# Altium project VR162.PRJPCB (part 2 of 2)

## Sheet 14 TP.SchDoc
size 246 x 182 mm
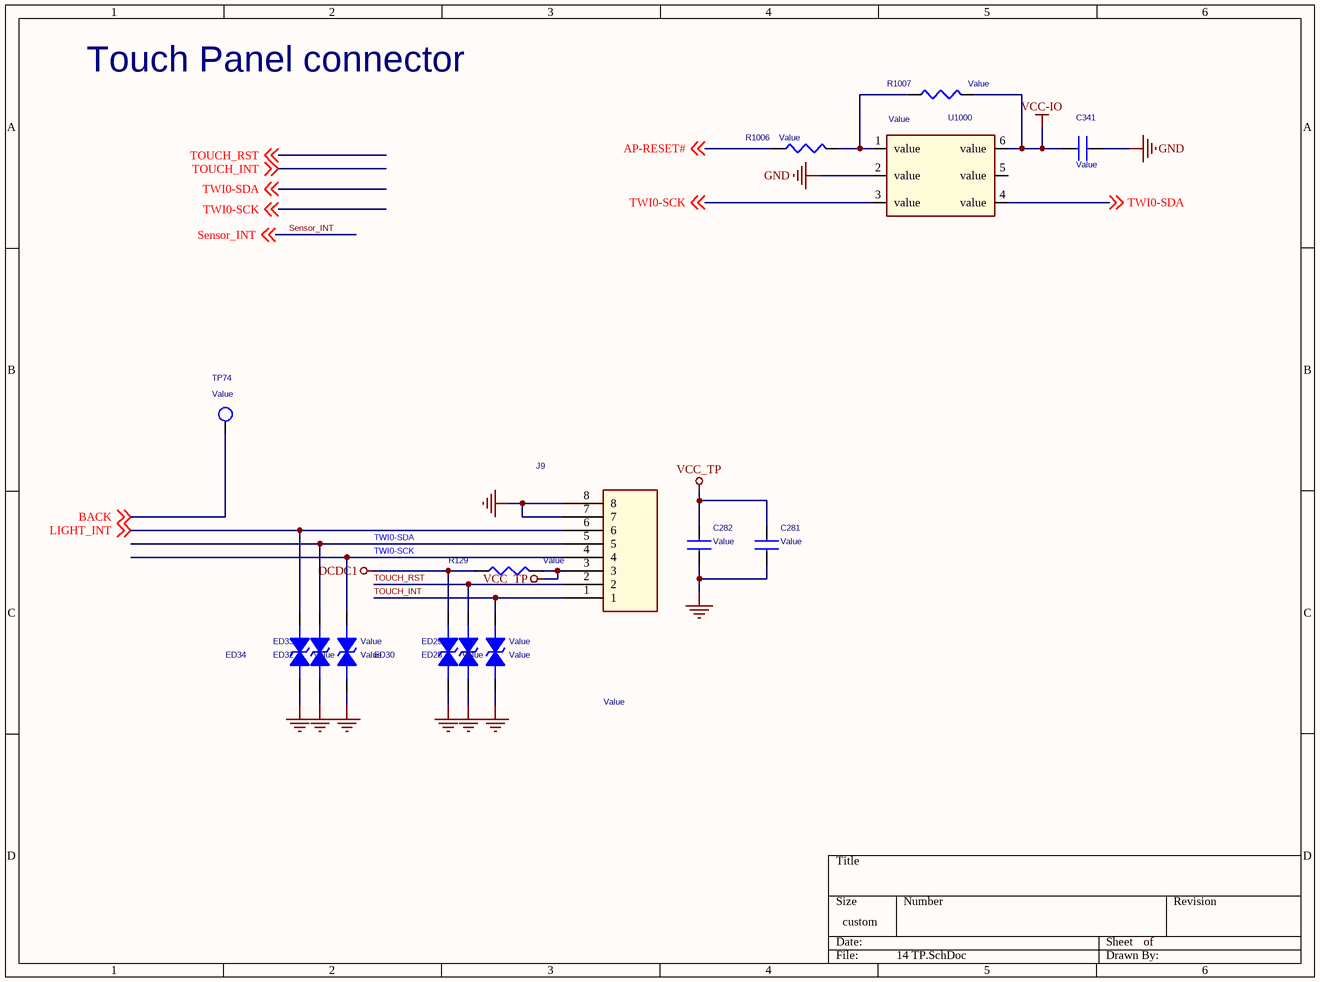
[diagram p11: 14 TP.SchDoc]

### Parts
C281  Value  [C0603]
C282  Value  [C0603]
C341  Value  [C0603]
ED28  Value  [R0402]
ED29  Value  [R0402]
ED30  Value  [R0402]
ED32  Value  [R0402]
ED33  Value  [R0402]
ED34  Value  [R0402]
J9  Value  [FPC8-PT0.5-H1_9A]
R129  Value  [R0402]
R1006  Value  [R0402]
R1007  Value  [R0402]
TP74  Value  [TP_SMD]
U1000  Value  [SOT23-6]

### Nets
DCDC1: C341.1 ED30.1 R129.1 R1007.2 U1000.6(value)  [also labelled VCC-IO]
GND: C281.2 C282.2 C341.2 ED28.2 ED29.2 ED30.2 ED32.2 ED33.2 ED34.2 J9.7 J9.8 U1000.2(value)
VCC_TP: C281.1 C282.1 J9.3 R129.2
AP-RESET#: R1006.1 ; off-sheet AP-RESET#
BACK: TP74.1(TP) ; off-sheet BACK
LIGHT_INT: ED34.1 J9.6 ; off-sheet LIGHT_INT
TOUCH_INT: ED28.1 J9.1 ; off-sheet TOUCH_INT
TOUCH_RST: ED29.1 J9.2 ; off-sheet TOUCH_RST
TWI0-SCK: ED32.1 J9.4 U1000.3(value) ; off-sheet TWI0-SCK  [project net SENSOR0-TWI-SCK]
TWI0-SDA: ED33.1 J9.5 U1000.4(value) ; off-sheet TWI0-SDA  [project net SENSOR0-TWI-SDA]
NetR1006_2: R1006.2 R1007.1 U1000.1(value)

Not connected (* = marked no-connect by the designer): U1000 5(value)

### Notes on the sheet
- Touch Panel connector

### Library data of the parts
C281 = CAP NP: CAP,MLCC,100nF,+/-10%,X7R,6.3V,SMD0402
C282 C341 = CAP NP
ED28-ED30 ED32-ED34 = DIODE BI-DIR TRIG: ESD
J9 = touch_screen_1
R129 = RESISTOR_Dup1: RES,thick film,33Ohm,+/-5%,1/16W,SMD0402
R1006 R1007 = R_Dup2
TP74 = T_POINT_R
U1000 = LM1086_2

## Sheet 09 CAMERA.SchDoc
size 386 x 246 mm
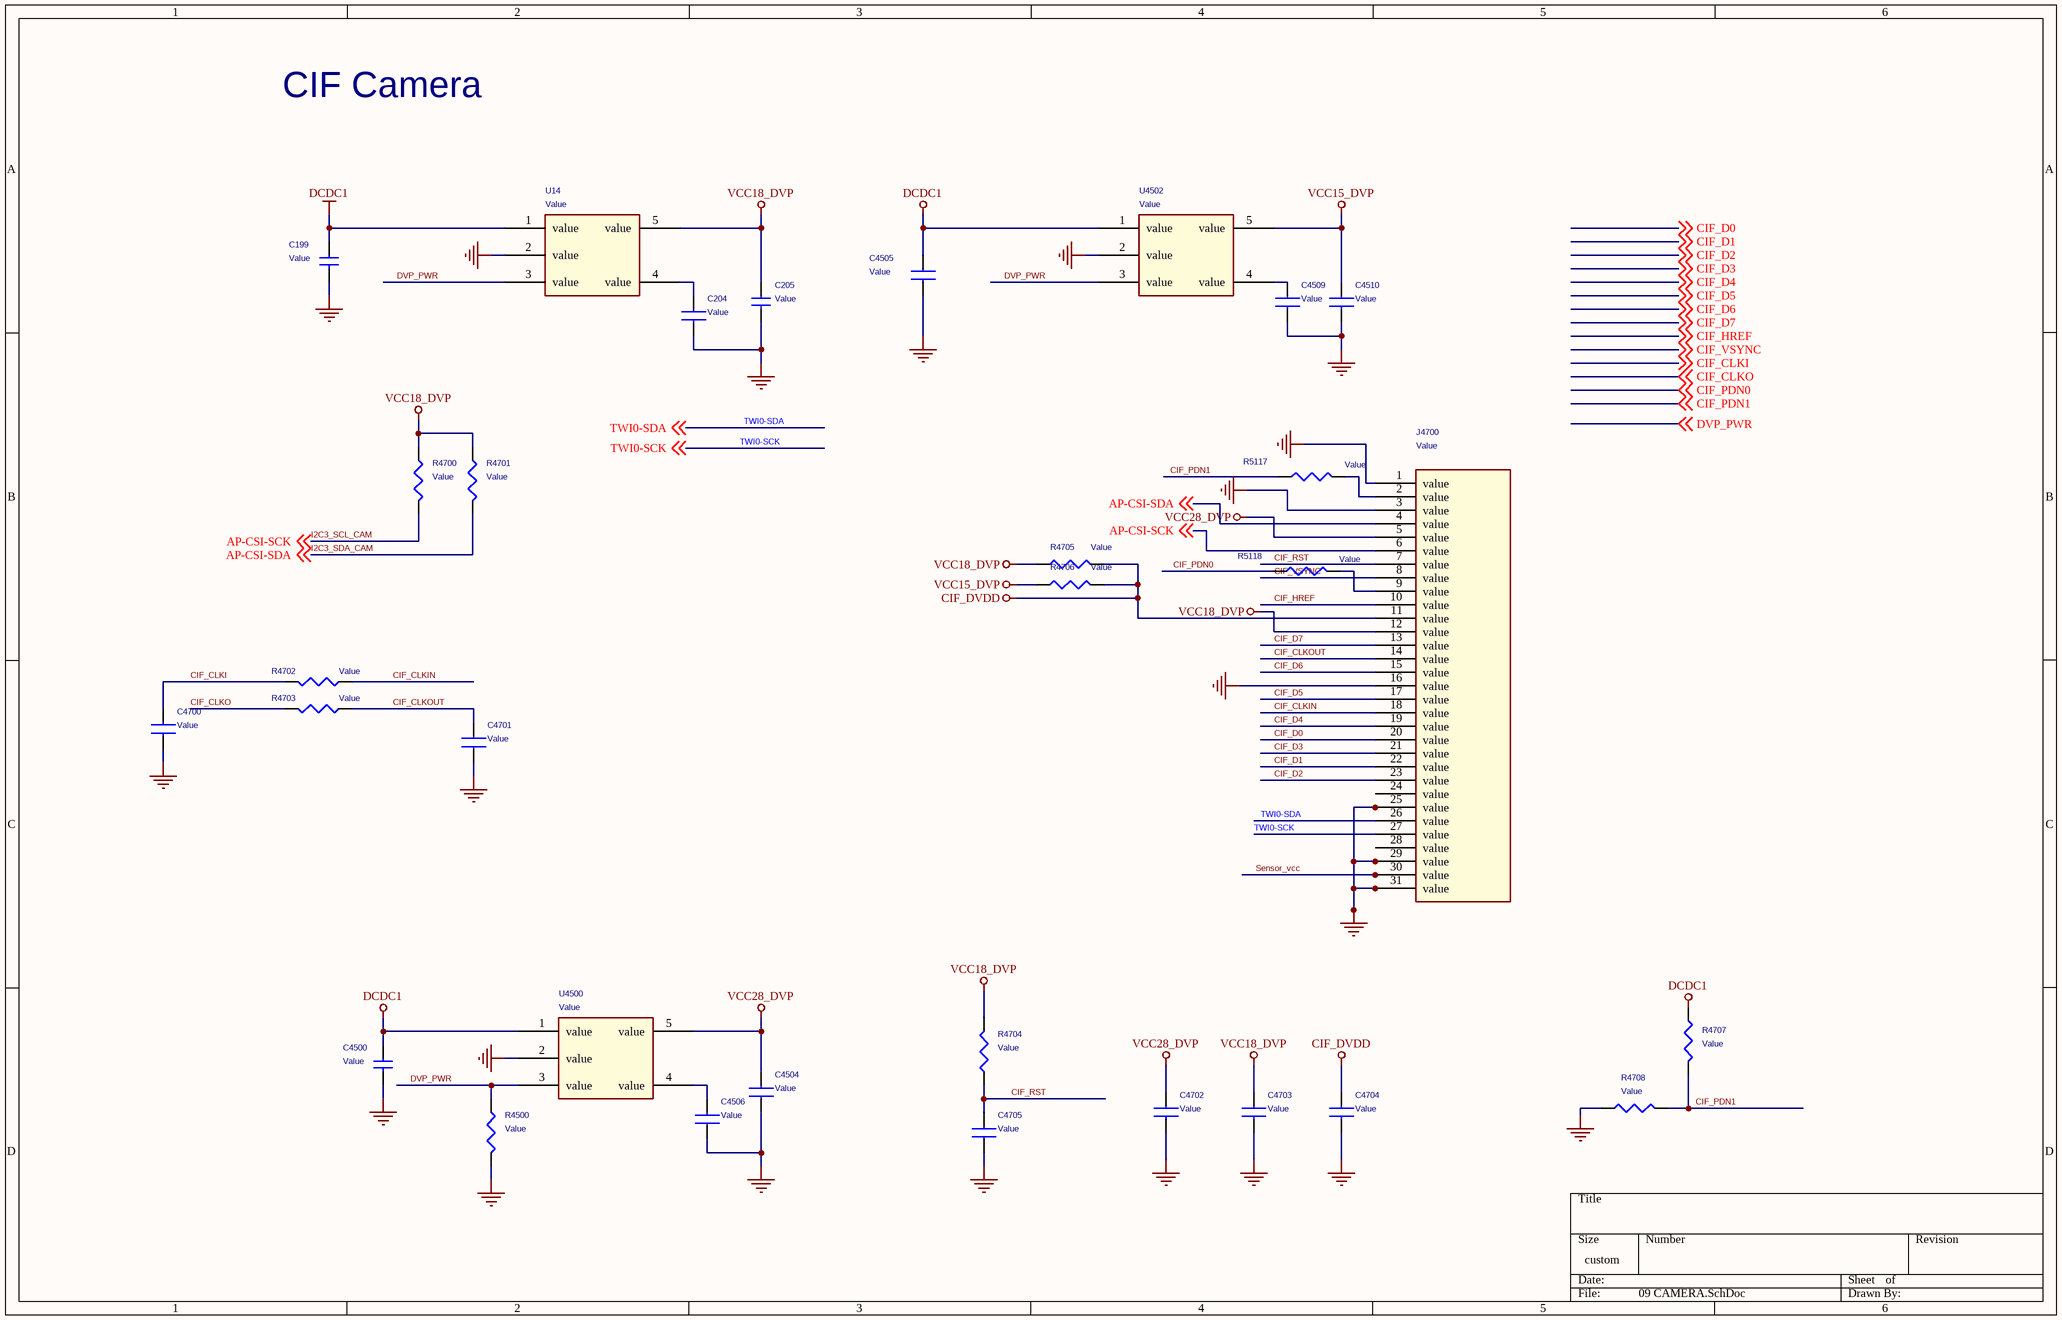
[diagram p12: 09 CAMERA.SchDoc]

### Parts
C199  Value  [C0603]
C204  Value  [C0603]
C205  Value  [C0603]
C4500  Value  [C0603]
C4504  Value  [C0603]
C4505  Value  [C0603]
C4506  Value  [C0603]
C4509  Value  [C0603]
C4510  Value  [C0603]
C4700  Value  [C0603]
C4701  Value  [C0603]
C4702  Value  [C0603]
C4703  Value  [C0603]
C4704  Value  [C0603]
C4705  Value  [C0603]
J4700  Value  [AYF333135]
R4500  Value  [R0402]
R4700  Value  [R0402]
R4701  Value  [R0402]
R4702  Value  [R0402]
R4703  Value  [R0402]
R4704  Value  [R0402]
R4705  Value  [R0402]
R4706  Value  [R0402]
R4707  Value  [R0402]
R4708  Value  [R0402]
R5117  Value  [R0402]
R5118  Value  [R0402]
U14  Value  [SOT23_5H14A]
U4500  Value  [SOT23_5H14A]
U4502  Value  [SOT23_5H14A]

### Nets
CIF_DVDD: C4704.2 J4700.11(value) R4705.2 R4706.2
DCDC1: C199.1 C4500.1 C4505.1 R4707.1 U14.1(value) U4500.1(value) U4502.1(value)
GND: C199.2 C204.2 C205.2 C4500.2 C4504.2 C4505.2 C4506.2 C4509.2 C4510.1 C4700.1 C4701.1 C4702.2 C4703.2 C4704.1 C4705.1 J4700.1(value) J4700.3(value) J4700.16(value) J4700.25(value) J4700.29(value) J4700.31(value) R4500.2 R4708.1 U14.2(value) U4500.2(value) U4502.2(value)
VCC15_DVP: C4510.2 R4706.1 U4502.5(value)
VCC18_DVP: C205.1 C4703.1 J4700.12(value) R4700.1 R4701.1 R4704.2 R4705.1 U14.5(value)
VCC28_DVP: C4504.1 C4702.1 J4700.5(value) U4500.5(value)
CIF_CLKI: C4700.2 R4702.2 ; off-sheet CIF_CLKI
CIF_CLKIN: J4700.18(value) R4702.1
CIF_CLKO: R4703.2 ; off-sheet CIF_CLKO
CIF_CLKOUT: C4701.2 J4700.14(value) R4703.1
CIF_D0: J4700.20(value) ; off-sheet CIF_D0
CIF_D1: J4700.22(value) ; off-sheet CIF_D1
CIF_D2: J4700.23(value) ; off-sheet CIF_D2
CIF_D3: J4700.21(value) ; off-sheet CIF_D3
CIF_D4: J4700.19(value) ; off-sheet CIF_D4
CIF_D5: J4700.17(value) ; off-sheet CIF_D5
CIF_D6: J4700.15(value) ; off-sheet CIF_D6
CIF_D7: J4700.13(value) ; off-sheet CIF_D7
CIF_HREF: J4700.10(value) ; off-sheet CIF_HREF
CIF_PDN0: R5118.1 ; off-sheet CIF_PDN0
CIF_PDN1: R4707.2 R4708.2 R5117.1 ; off-sheet CIF_PDN1
CIF_RST: C4705.2 J4700.7(value) R4704.1
CIF_VSYNC: J4700.8(value) ; off-sheet CIF_VSYNC
DVP_PWR: R4500.1 U14.3(value) U4500.3(value) U4502.3(value) ; off-sheet DVP_PWR
I2C3_SCL_CAM: J4700.6(value) R4700.2 ; off-sheet AP-CSI-SCK  [also labelled AP-CSI-SCK]
I2C3_SDA_CAM: J4700.4(value) R4701.2 ; off-sheet AP-CSI-SDA  [also labelled AP-CSI-SDA]
Sensor_vcc: J4700.30(value)
TWI0-SCK: J4700.27(value) ; off-sheet TWI0-SCK  [project net SENSOR0-TWI-SCK]
TWI0-SDA: J4700.26(value) ; off-sheet TWI0-SDA  [project net SENSOR0-TWI-SDA]
NetC204_1: C204.1 U14.4(value)
NetC4506_1: C4506.1 U4500.4(value)
NetC4509_1: C4509.1 U4502.4(value)
NetJ4700_2: J4700.2(value) R5117.2
NetJ4700_9: J4700.9(value) R5118.2

Not connected (* = marked no-connect by the designer): J4700 24(value) 28(value)

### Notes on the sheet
- CIF Camera

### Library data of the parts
C199 C205 C4500 = SMALL CAP: 贴片电容
C204 C4505 C4506 C4509 C4510 = CAP NP
C4504 C4705 = CAP NP: CAP,MLCC,100nF,+/-10%,X7R,6.3V,SMD0402
C4700 C4701 = CAP NP: CAP,MLCC,8pF,+/-10%,NPO,6.3V,SMD0402
C4702-C4704 = CAP NP: CAP,MLCC,1uF,+/-10%,X5R,6.3V,SMD0402
J4700 = LCM0200CE1A0_2: Camera Conncetor, 24pin,SMT
R4500 = RES 1B
R4700 R4701 R4705-R4708 R5117 R5118 = RESISTOR_0_Dup1
R4702 R4703 = RESISTOR_0: RES,thick film,22Ohm,+/-5%,1/16W,SMD0402
R4704 = RESISTOR: NC
U14 U4500 U4502 = LDO-PT5108/RT9013_0

## Sheet 15 SENSOR.SchDoc
size 386 x 246 mm
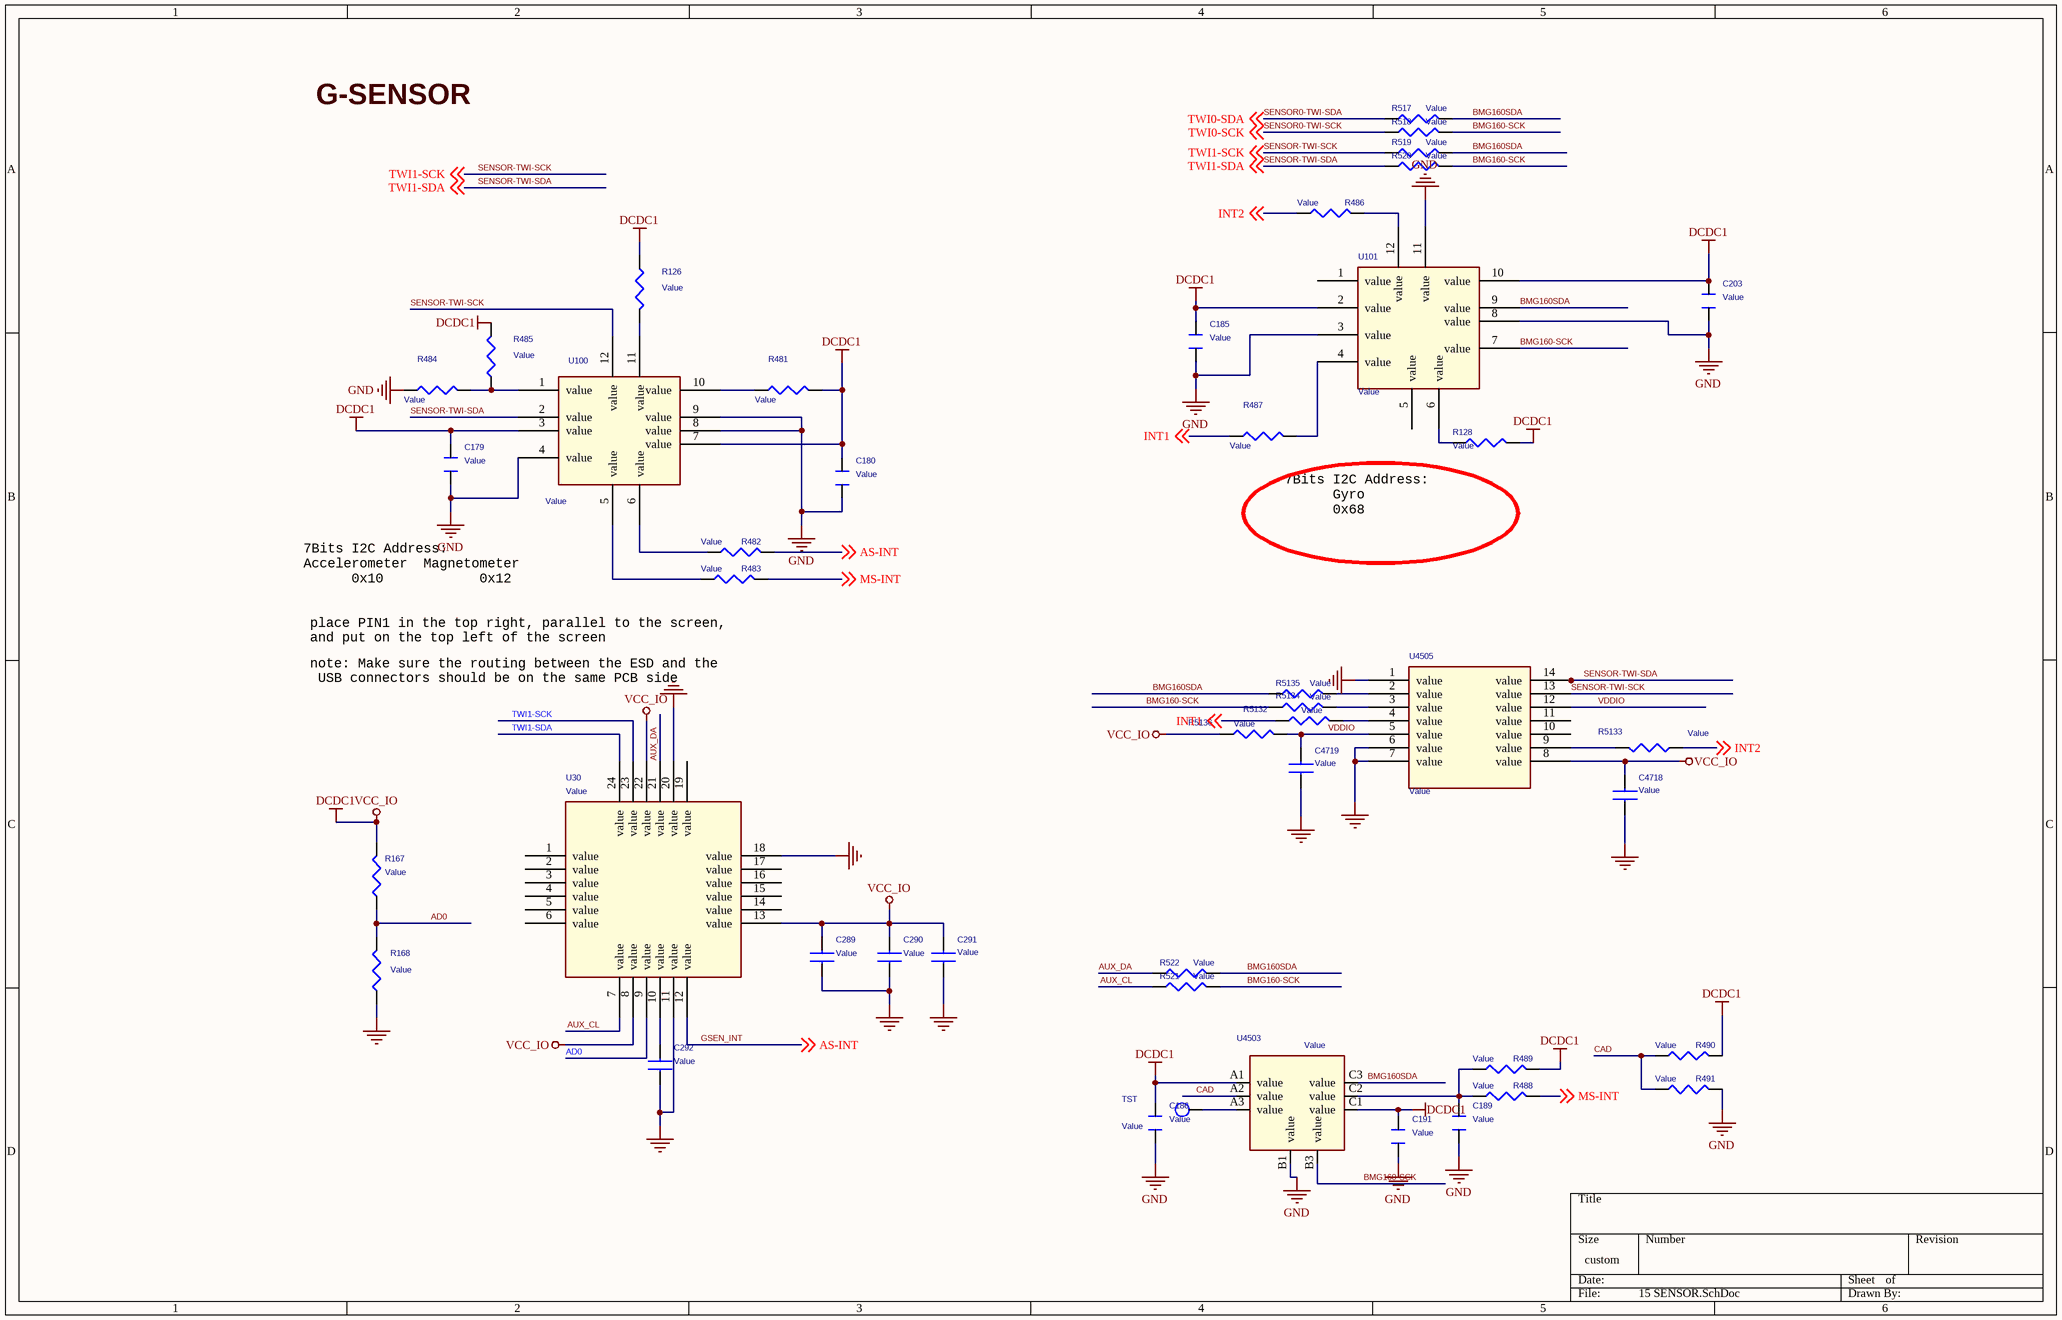
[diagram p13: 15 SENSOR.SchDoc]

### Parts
C179  Value  [C0402]
C180  Value  [C0402]
C185  Value  [C0402]
C186  Value  [C0402]
C189  Value  [C0402]
C191  Value  [C0402]
C203  Value  [C0402]
C289  Value  [C0603]
C290  Value  [C0603]
C291  Value  [C0603]
C292  Value  [C0603]
C4718  Value  [C0603]
C4719  Value  [C0603]
R126  Value  [R0402]
R128  Value  [R0402]
R167  Value  [R0402]
R168  Value  [R0402]
R481  Value  [R0402]
R482  Value  [R0402]
R483  Value  [R0402]
R484  Value  [R0402]
R485  Value  [R0402]
R486  Value  [R0402]
R487  Value  [R0402]
R488  Value  [R0402]
R489  Value  [R0402]
R490  Value  [R0402]
R491  Value  [R0402]
R517  Value  [R0402]
R518  Value  [R0402]
R519  Value  [R0402]
R520  Value  [R0402]
R521  Value  [R0402]
R522  Value  [R0402]
R5132  Value  [R0402]
R5133  Value  [R0402]
R5134  Value  [R0402]
R5135  Value  [R0402]
R5136  Value  [R0402]
TST  Value  [TP_SMD]
U30  Value  [QFN24-3X3]
U100  Value  [BGA156]
U101  Value  [BGA160]
U4503  Value  [AK09911]
U4505  Value  [BMI160]

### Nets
DCDC1: C179.2 C180.2 C185.2 C186.2 C191.2 C203.2 C289.1 C290.2 C291.2 C4718.2 R126.1 R128.2 R167.2 R481.2 R485.2 R489.2 R490.2 R5136.1 U30.8(value) U30.13(value) U30.22(value) U100.3(value) U100.7(value) U101.2(value) U101.10(value) U4503.A1(value) U4503.C1(value) U4505.8(value)  [also labelled VCC_IO]
GND: C179.1 C180.1 C185.1 C186.1 C189.1 C191.1 C203.1 C289.2 C290.1 C291.1 C292.2 C4718.1 C4719.1 R168.1 R484.1 R491.2 U30.11(value) U30.18(value) U30.20(value) U100.4(value) U100.8(value) U100.9(value) U101.3(value) U101.8(value) U101.11(value) U4503.B1(value) U4505.1(value) U4505.6(value) U4505.7(value)
AD0: R167.1 R168.2 U30.9(value)
AUX_CL: R521.1 U30.7(value)
AUX_DA: R522.1 U30.21(value)
BMG160-SCK: R518.2 R520.2 R521.2 R5134.1 U101.7(value) U4503.B3(value)
BMG160SDA: R517.2 R519.2 R522.2 R5135.1 U101.9(value) U4503.C3(value)
CAD: R490.1 R491.1 U4503.A2(value)
GSEN_INT: R482.2 U30.12(value) ; off-sheet AS-INT  [also labelled AS-INT]
INT1: R487.1 R5132.1 ; off-sheet INT1
INT2: R486.1 R5133.1 ; off-sheet INT2
MS-INT: R483.2 R488.2 ; off-sheet MS-INT
SENSOR0-TWI-SCK: R518.1 ; off-sheet TWI0-SCK  [also labelled TWI0-SCK]
SENSOR0-TWI-SDA: R517.1 ; off-sheet TWI0-SDA  [also labelled TWI0-SDA]
SENSOR-TWI-SCK: R519.1 U30.23(value) U100.12(value) U4505.13(value) ; off-sheet TWI1-SCK  [also labelled TWI1-SCK]
SENSOR-TWI-SDA: R520.1 U30.24(value) U100.2(value) U4505.14(value) ; off-sheet TWI1-SDA  [also labelled TWI1-SDA]
VDDIO: C4719.2 R5136.2 U4505.5(value) U4505.12(value)
NetC189_2: C189.2 R488.1 R489.1 U4503.C2(value)
NetC292_1: C292.1 U30.10(value)
NetR126_2: R126.2 U100.11(value)
NetR128_1: R128.1 U101.6(value)
NetR481_1: R481.1 U100.10(value)
NetR482_1: R482.1 U100.6(value)
NetR483_1: R483.1 U100.5(value)
NetR484_2: R484.2 R485.1 U100.1(value)
NetR486_2: R486.2 U101.12(value)
NetR487_2: R487.2 U101.4(value)
NetR5132_2: R5132.2 U4505.4(value)
NetR5133_2: R5133.2 U4505.9(value)
NetR5134_2: R5134.2 U4505.3(value)
NetR5135_2: R5135.2 U4505.2(value)
NetTST_1: TST.1(TP) U4503.A3(value)

Not connected (* = marked no-connect by the designer): U30 1(value) 2(value) 3(value) 4(value) 5(value) 6(value) 14(value) 15(value) 16(value) 17(value) 19(value); U101 1(value) 5(value); U4505 10(value) 11(value)

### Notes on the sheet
- G-SENSOR
- 7Bits I2C Address:
  Gyro
  0x68
- 7Bits I2C Address:
  Accelerometer  Magnetometer
  0x10            0x12
- (near R483) place PIN1 in the top right, parallel to the screen,
  and put on the top left of the screen
- note: Make sure the routing between the ESD and the
  USB connectors should be on the same PCB side

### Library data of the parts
C179 C180 C185 C186 C189 C191 C203 = CAPACITOR_0_Dup3: PAGE: 2
C289 = CAP NP: CAP,MLCC,100nF,+/-10%,X7R,6.3V,SMD0402
C290 C292 = CAP NP: CAP,MLCC,1uF,+/-10%,X5R,6.3V,SMD0402; ROOM: CHG
C291 C4718 C4719 = CAP NP: RoHS CHIP CAP 0.1uF +10/-10% X7R
R126 R128 R481-R491 R517-R522 R5132-R5136 = R_Dup1
R167 = RESISTOR_0: NC
R168 = RESISTOR_0: RES,thick film,0Ohm,+/-5%,1/16W,SMD0402
TST = T_POINT_R
U30 = Sensor_MPU6500_0
U100 = BMC156_0
U101 = BMG160_1
U4503 = AK09911_0
U4505 = BMG160_0

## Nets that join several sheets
ALDO1: 07 POWER (C74.2 R328.2 U28.R6), 06 CPU (7 pins)
ALDO2: 12 CODEC (C197.1 C230.2 U28.H2), 07 POWER (C76.2 U28.T4), 06 CPU (5 pins), 05 LPDDR3_32X1 (14 pins)
ALDO3: 12 CODEC (C227.2 R162.2 U28.C2), 07 POWER (C78.2 U28.T5), 06 CPU (C11.2 U1.T15)
BB-VBAT: 13 WIFI+BT (C234.2 U24.9), 07 POWER (11 pins)
DC1-SW: 10 MIPI DSI (10 pins), 07 POWER (C273.1 U28.J5)
DCDC1: 12 CODEC (C228.2 R5123.1 U28.N2), 11 CARD-SENSOR-VIBRATOR (7 pins), 08 NAND-eMMC (16 pins), 07 POWER (10 pins), 06 CPU (11 pins), 14 TP (5 pins), 09 CAMERA (7 pins), 15 SENSOR (28 pins)
DCDC6: 07 POWER (C69.2 L7.2 U28.E12), 06 CPU (11 pins)
DLDO1: 13 WIFI+BT (16 pins), 12 CODEC (C229.2 U28.J2), 07 POWER (C279.1 U28.F7)
FLDO1: 07 POWER (C89.2 U28.E15), 06 CPU (U1.P14)
FLDO2: 07 POWER (C90.2 U28.F14), 06 CPU (C17.2 C18.2 U1.R17 U1.T17)
GND: 13 WIFI+BT (28 pins), 12 CODEC (32 pins), 11 CARD-SENSOR-VIBRATOR (41 pins), 10 MIPI DSI (42 pins), 08 NAND-eMMC (17 pins), 07 POWER (142 pins), 06 CPU (85 pins), 05 LPDDR3_32X1 (70 pins), 14 TP (12 pins), 09 CAMERA (26 pins), 15 SENSOR (29 pins)
PS: 12 CODEC (C333.1 FB3.1), 10 MIPI DSI (C130.2 C131.2 L9.1 U11.6), 07 POWER (32 pins)
USB-5V: 11 CARD-SENSOR-VIBRATOR (C182.2 U19.5), 07 POWER (C93.2 C94.2 OD1.2 R22.1)
USBVBUS: 11 CARD-SENSOR-VIBRATOR (5 pins), 07 POWER (C266.2 R463.2 U28.R16)
VCC-DRAM: 07 POWER (5 pins), 05 LPDDR3_32X1 (66 pins)
VCC-PD: 07 POWER (R328.1 R329.1), 06 CPU (C4.1 U1.F13 U1.F14)
VCC-RTC: 12 CODEC (5 pins), 07 POWER (C70.2 U28.T14), 06 CPU (7 pins)
VDD-CPUA: 07 POWER (C56.1 L2.2), 06 CPU (13 pins)
VDD-CPUB: 07 POWER (C59.1 L3.2), 06 CPU (13 pins)
VDD-GPU: 07 POWER (C63.1 L5.2 U28.N4), 06 CPU (9 pins)
AP-CK32KO: 13 WIFI+BT (R464.2 R465.2), 12 CODEC (U28.C7)
AP-I2S-BCLK: 12 CODEC (U28.R2), 06 CPU (U1.A10)
AP-I2S-DIN: 12 CODEC (U28.P2), 06 CPU (U1.B9)
AP-I2S-DOUT0: 12 CODEC (U28.P1), 06 CPU (U1.E9)
AP-I2S-LRCK: 12 CODEC (U28.R1), 06 CPU (U1.C9)
AP-I2S-MCLK: 12 CODEC (U28.T2), 06 CPU (U1.C8)
AP-NMI#: 12 CODEC (R33.2 U28.A11), 06 CPU (C280.2 U1.Y16)
AP-RESET#: 10 MIPI DSI (R93.1), 07 POWER (C79.2 R17.2), 06 CPU (C277.1 U1.AA16), 14 TP (R1006.1)
AP-WAKE-BT: 13 WIFI+BT (R193.2 U24.6), 06 CPU (U1.W7)
BACK: 11 CARD-SENSOR-VIBRATOR (R135.2), 14 TP (TP74.1)
BT-PCM-CLK: 13 WIFI+BT (U24.26), 12 CODEC (U28.K2)
BT-PCM-DIN: 13 WIFI+BT (U24.27), 12 CODEC (U28.K1)
BT-PCM-DOUT: 13 WIFI+BT (U24.25), 12 CODEC (U28.J1)
BT-PCM-SYNC: 13 WIFI+BT (U24.28), 12 CODEC (U28.J3)
BT-UART-CTS: 13 WIFI+BT (R182.2 U24.44), 06 CPU (U1.N18)
BT-UART-RTS: 13 WIFI+BT (R179.2 U24.41), 06 CPU (U1.N19)
BT-UART-RX: 13 WIFI+BT (R181.2 U24.43), 06 CPU (U1.M19)
BT-UART-TX: 13 WIFI+BT (R180.2 U24.42), 06 CPU (U1.N16)
BT-WAKE-AP: 13 WIFI+BT (U24.7), 06 CPU (U1.W17)
CIF_CLKI: 06 CPU (U1.E15), 09 CAMERA (C4700.2 R4702.2)
CIF_CLKO: 06 CPU (U1.E16), 09 CAMERA (R4703.2)
CIF_D0: 06 CPU (U1.D15), 09 CAMERA (J4700.20)
CIF_D1: 06 CPU (U1.F15), 09 CAMERA (J4700.22)
CIF_D2: 06 CPU (U1.E13), 09 CAMERA (J4700.23)
CIF_D3: 06 CPU (U1.D13), 09 CAMERA (J4700.21)
CIF_D4: 06 CPU (U1.B14), 09 CAMERA (J4700.19)
CIF_D5: 06 CPU (U1.F17), 09 CAMERA (J4700.17)
CIF_D6: 06 CPU (U1.C14), 09 CAMERA (J4700.15)
CIF_D7: 06 CPU (U1.E12), 09 CAMERA (J4700.13)
CIF_HREF: 06 CPU (U1.D16), 09 CAMERA (J4700.10)
CIF_PDN0: 06 CPU (U1.B12), 09 CAMERA (R5118.1)
CIF_PDN1: 06 CPU (U1.A12), 09 CAMERA (R4707.2 R4708.2 R5117.1)
CIF_VSYNC: 06 CPU (U1.C15), 09 CAMERA (J4700.8)
CODEC-SCK: 12 CODEC (R473.2 U28.B10), 06 CPU (U1.AA15)
CODEC-SDA: 12 CODEC (R474.2 U28.C9), 06 CPU (U1.W14)
DSI-CKN: 10 MIPI DSI (OLED1.18), 06 CPU (U1.G18)
DSI-CKP: 10 MIPI DSI (OLED1.16), 06 CPU (U1.G19)
DSI-D0N: 10 MIPI DSI (OLED1.26), 06 CPU (U1.H20)
DSI-D0P: 10 MIPI DSI (OLED1.24), 06 CPU (U1.J19)
DSI-D1N: 10 MIPI DSI (OLED1.22), 06 CPU (U1.G20)
DSI-D1P: 10 MIPI DSI (OLED1.20), 06 CPU (U1.H19)
DSI-D2N: 10 MIPI DSI (OLED1.14), 06 CPU (U1.F21)
DSI-D2P: 10 MIPI DSI (OLED1.12), 06 CPU (U1.G21)
DSI-D3N: 10 MIPI DSI (OLED1.10), 06 CPU (U1.F19)
DSI-D3P: 10 MIPI DSI (OLED1.8), 06 CPU (U1.F20)
DVP_PWR: 06 CPU (U1.D12), 09 CAMERA (R4500.1 U14.3 U4500.3 U4502.3)
eMMC-CLK: 08 NAND-eMMC (U29.W6), 06 CPU (R28.1)
eMMC-CMD: 08 NAND-eMMC (R26.2 R27.2 R29.2 U29.W5), 06 CPU (U1.W11)
eMMC-D0: 08 NAND-eMMC (U29.H3), 06 CPU (U1.T10)
eMMC-D1: 08 NAND-eMMC (U29.H4), 06 CPU (U1.U10)
eMMC-D2: 08 NAND-eMMC (U29.H5), 06 CPU (U1.V10)
eMMC-D3: 08 NAND-eMMC (U29.J2), 06 CPU (U1.W10)
eMMC-D4: 08 NAND-eMMC (U29.J3), 06 CPU (U1.Y10)
eMMC-D5: 08 NAND-eMMC (U29.J4), 06 CPU (U1.AA10)
eMMC-D6: 08 NAND-eMMC (U29.J5), 06 CPU (U1.T9)
eMMC-D7: 08 NAND-eMMC (U29.J6), 06 CPU (U1.V9)
eMMC-RST: 08 NAND-eMMC (U29.U5), 06 CPU (U1.W9)
GSEN_INT: 06 CPU (U1.P19), 15 SENSOR (R482.2 U30.12)
I2C3_SCL_CAM: 06 CPU (U1.C12), 09 CAMERA (J4700.6 R4700.2)
I2C3_SDA_CAM: 06 CPU (U1.B13), 09 CAMERA (J4700.4 R4701.2)
INT2: 06 CPU (U1.V7), 15 SENSOR (R486.1 R5133.1)
IRQ-AUDIO: 12 CODEC (R162.1 U28.L1), 06 CPU (U1.AA19)
LCD-BL-EN: 10 MIPI DSI (R90.1 R92.2), 06 CPU (U1.C18)
LCD-PWM: 10 MIPI DSI (R86.1 R88.1), 06 CPU (U1.C17)
LIGHT_INT: 06 CPU (U1.Y6), 14 TP (ED34.1 J9.6)
MS-INT: 06 CPU (U1.N21), 15 SENSOR (R483.2 R488.2)
NRB1: 08 NAND-eMMC (R24.2 R25.1), 06 CPU (U1.Y11)
PA-SHDN: 12 CODEC (R5120.2 R5123.2), 06 CPU (U1.U16)
PWRON: 11 CARD-SENSOR-VIBRATOR (ED25.1 J3.4), 07 POWER (R12.2 TP61.1)
RED_LED: 11 CARD-SENSOR-VIBRATOR (R479.2), 06 CPU (U1.W6)
SDC0-CLK: 11 CARD-SENSOR-VIBRATOR (D18.1 J8.5), 06 CPU (R125.2)
SDC0-CMD: 11 CARD-SENSOR-VIBRATOR (D19.1 J8.3 R122.2), 06 CPU (U1.W4)
SDC0-D0: 11 CARD-SENSOR-VIBRATOR (D17.1 J8.7), 06 CPU (U1.Y4)
SDC0-D1: 11 CARD-SENSOR-VIBRATOR (D16.1 J8.8), 06 CPU (U1.Y5)
SDC0-D2: 11 CARD-SENSOR-VIBRATOR (D15.1 J8.1), 06 CPU (U1.Y3)
SDC0-D3: 11 CARD-SENSOR-VIBRATOR (D20.1 J8.2), 06 CPU (U1.AA3)
SDC0-DET: 11 CARD-SENSOR-VIBRATOR (D21.1 J8.9 R123.2), 06 CPU (U1.AA2)
SENSOR0-TWI-SCK: 06 CPU (R497.1 U1.U9), 14 TP (ED32.1 J9.4 U1000.3), 09 CAMERA (J4700.27), 15 SENSOR (R518.1)
SENSOR0-TWI-SDA: 06 CPU (R498.1 U1.W8), 14 TP (ED33.1 J9.5 U1000.4), 09 CAMERA (J4700.26), 15 SENSOR (R517.1)
SENSOR-TWI-SCK: 06 CPU (R6.1 U1.Y8), 15 SENSOR (R519.1 U30.23 U100.12 U4505.13)
SENSOR-TWI-SDA: 06 CPU (R7.1 U1.AA7), 15 SENSOR (R520.1 U30.24 U100.2 U4505.14)
TOUCH_INT: 06 CPU (U1.Y18), 14 TP (ED28.1 J9.1)
TOUCH_RST: 06 CPU (U1.W18), 14 TP (ED29.1 J9.2)
UBOOT: 11 CARD-SENSOR-VIBRATOR (D38.1 SW8.1), 06 CPU (U1.U15)
USB-DM0: 11 CARD-SENSOR-VIBRATOR (D31.1 USB1.2), 06 CPU (U1.W20)
USB-DP0: 11 CARD-SENSOR-VIBRATOR (D30.1 USB1.3), 06 CPU (U1.W21)
USB-DRVVBUS: 11 CARD-SENSOR-VIBRATOR (R139.2 U19.4), 07 POWER (U28.T16)
USB-ID: 11 CARD-SENSOR-VIBRATOR (R140.1), 06 CPU (U1.N20)
VDDFB-CPUA: 07 POWER (U28.T11), 06 CPU (U1.M10)
VDDFB-CPUB: 07 POWER (U28.R11), 06 CPU (U1.J12)
WHITE_LED: 11 CARD-SENSOR-VIBRATOR (R477.1), 06 CPU (U1.V6)
WL-SDIO-CLK: 13 WIFI+BT (C315.2 R195.1), 06 CPU (U1.K17)
WL-SDIO-CMD: 13 WIFI+BT (C314.2 R176.2 U24.16), 06 CPU (U1.K18)
WL-SDIO-D0: 13 WIFI+BT (C316.2 R174.2 U24.18), 06 CPU (U1.L19)
WL-SDIO-D1: 13 WIFI+BT (C317.2 R173.2 U24.19), 06 CPU (U1.M16)
WL-SDIO-D2: 13 WIFI+BT (C312.2 R178.2 U24.14), 06 CPU (U1.M17)
WL-SDIO-D3: 13 WIFI+BT (C313.2 R177.2 U24.15), 06 CPU (U1.M18)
